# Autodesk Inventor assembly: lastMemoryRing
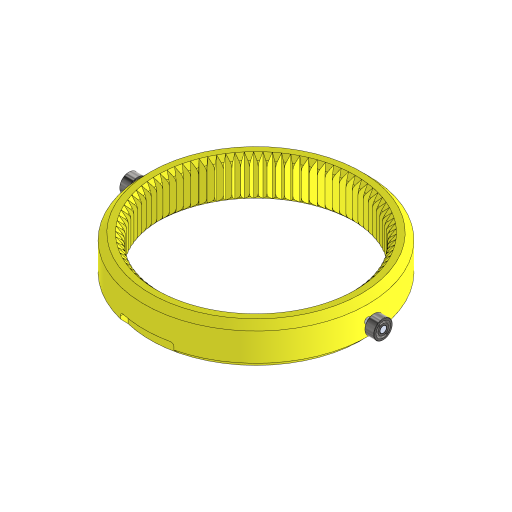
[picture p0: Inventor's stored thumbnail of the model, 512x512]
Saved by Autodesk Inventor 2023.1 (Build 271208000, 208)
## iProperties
Created: 2021-02
Part Number: lastMemoryRing
Document SubType Name: Assembly
Designer: ftrauzettel
Author: ftrauzettel
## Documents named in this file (4)
- C:\Users\Fabian\OneDrive\Delft\CPMM\Machined_Prototype\Mods\Assemblies\subAssemblies\lastMemoryRing.iam
- C:\Users\Fabian\OneDrive\Delft\CPMM\Machined_Prototype\Mods\Parts\original parts\Memory ring - last.ipt
- C:\Users\Fabian\OneDrive\Delft\CPMM\Machined_Prototype\Mods\Parts\original parts\Bearing pin.ipt
- C:\Users\Fabian\OneDrive\Delft\CPMM\Machined_Prototype\Mods\ContentCenter\en-US\ISO 1224-1 M\ISO 1224-1 - 38 - 1 x 3 x 1.5.ipt
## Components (5 placed, 3 different names)
1. Memory ring - last:2 — Mate:2, Mate:3
2. ISO 1224-1 (Metric) 38 - 1 x 3 x 1.5:1 — Mate:1, Flush:1
3. Bearing pin:1 — Mate:1, Flush:1, Mate:2, Mate:3
4. ISO 1224-1 (Metric) 38 - 1 x 3 x 1.5:2
5. Bearing pin:2
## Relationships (4: Mate 3, Flush 1)
- Mate:1: ISO 1224-1 (Metric) 38 - 1 x 3 x 1.5:1 ↔ Bearing pin:1
- Flush:1: ISO 1224-1 (Metric) 38 - 1 x 3 x 1.5:1 ↔ Bearing pin:1
- Mate:2: Memory ring - last:2 ↔ Bearing pin:1
- Mate:3: Memory ring - last:2 ↔ Bearing pin:1
